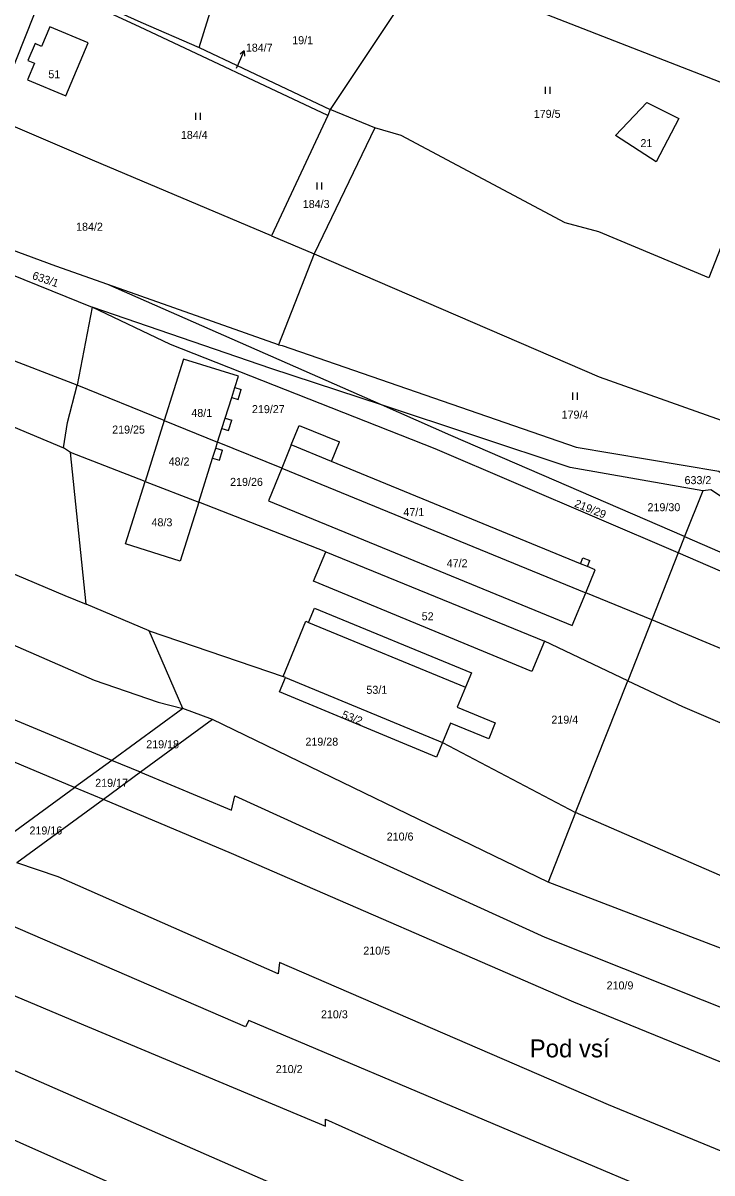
# Model space of a CAD drawing. Extents: x -744566 to -741843, y -1128407 to -1126744.
# Drawn here: x -742903.8 to -742757.6, y -1127789.3 to -1127545.1 of the extents above; entities that cross this region are included whole.
import ezdxf

# ---------------------------------------------------------------- set-up
doc = ezdxf.new("R2010")
doc.units = 0
for name, color, linetype in [('Hranice parcel', 7, 'Continuous'), ('Parcelní čísla', 7, 'Continuous'), ('Pop  PČ popisy', 7, 'Continuous'), ('Vnitřní kresba', 7, 'Continuous'), ('Značky kultur', 7, 'Continuous')]:
    doc.layers.add(name, color=color, linetype=linetype)

msp = doc.modelspace()

# ---------------------------------------------------------------- linework, layer by layer
at = {"layer": 'Hranice parcel'}
for p, q in [((-742818.41, -1127533.18), (-742838.56, -1127563.45)), ((-742818.41, -1127533.18), (-742743.76, -1127562.35)), ((-742866.42, -1127550.29), (-742838.56, -1127563.45)), ((-742838.56, -1127563.45), (-742839.05, -1127564.77)), ((-742829.14, -1127567.37), (-742838.56, -1127563.45)), ((-742839.05, -1127564.77), (-742851.05, -1127590.28)), ((-742829.14, -1127567.37), (-742842.01, -1127594.12)), ((-742851.05, -1127590.28), (-742842.01, -1127594.12)), ((-742919.33, -1127593.19), (-742889.07, -1127605.41)), ((-742842.01, -1127594.12), (-742849.54, -1127613.47)), ((-742827.7, -1127626.22), (-742885.79, -1127600.64)), ((-742849.54, -1127613.47), (-742885.79, -1127600.64)), ((-742889.07, -1127605.41), (-742892.31, -1127622.04)), ((-742892.31, -1127622.04), (-742925.74, -1127609.17)), ((-742873.81, -1127629.53), (-742892.31, -1127622.04)), ((-742873.81, -1127629.53), (-742877.87, -1127642.45)), ((-742873.81, -1127629.53), (-742862.47, -1127634.12)), ((-742848.87, -1127639.63), (-742862.47, -1127634.12)), ((-742893.68, -1127636.29), (-742895.2, -1127635.33)), ((-742890.34, -1127668.53), (-742893.68, -1127636.29)), ((-742877.87, -1127642.45), (-742893.68, -1127636.29)), ((-742848.87, -1127639.63), (-742784.35, -1127666.12)), ((-742877.87, -1127642.45), (-742866.48, -1127646.88)), ((-742839.52, -1127657.38), (-742866.48, -1127646.88)), ((-742759.53, -1127644.48), (-742763.36, -1127654.17)), ((-742763.36, -1127654.17), (-742764.73, -1127657.63)), ((-742839.52, -1127657.38), (-742793.13, -1127676.4)), ((-742764.73, -1127657.63), (-742770.35, -1127671.87)), ((-742770.35, -1127671.87), (-742784.35, -1127666.12)), ((-742877.02, -1127674.2), (-742890.34, -1127668.53)), ((-742770.35, -1127671.87), (-742775.45, -1127684.77)), ((-742877.02, -1127674.2), (-742848.58, -1127683.87)), ((-742869.86, -1127690.69), (-742877.02, -1127674.2)), ((-742775.45, -1127684.77), (-742793.13, -1127676.4)), ((-742848.05, -1127684.09), (-742848.58, -1127683.87)), ((-742848.05, -1127684.09), (-742814.73, -1127697.87)), ((-742786.49, -1127712.73), (-742775.45, -1127684.77)), ((-742869.86, -1127690.69), (-742884.93, -1127701.69)), ((-742863.54, -1127693.04), (-742869.86, -1127690.69)), ((-742863.54, -1127693.04), (-742878.82, -1127704.23)), ((-742792.35, -1127727.57), (-742863.54, -1127693.04)), ((-742814.73, -1127697.87), (-742786.49, -1127712.73)), ((-742884.93, -1127701.69), (-742892.82, -1127707.45)), ((-742878.82, -1127704.23), (-742884.93, -1127701.69)), ((-742878.82, -1127704.23), (-742886.72, -1127710.02)), ((-742911.19, -1127720.85), (-742892.82, -1127707.45)), ((-742886.72, -1127710.02), (-742892.82, -1127707.45)), ((-742886.72, -1127710.02), (-742905.07, -1127723.45)), ((-742786.49, -1127712.73), (-742792.35, -1127727.57)), ((-742663.65, -1127776.96), (-742792.35, -1127727.57))]:
    msp.add_line(p, q, dxfattribs=at)
for points in [[(-742866.42, -1127550.29), (-742864.4, -1127543.94), (-742860.9, -1127533.04), (-742859.94, -1127530.06), (-742866.48, -1127528.08), (-742868.86, -1127527.7), (-742866.81, -1127522.06)], [(-742839.05, -1127564.77), (-742879.04, -1127545.88), (-742898.83, -1127536.68)], [(-742898.55, -1127535.95), (-742878.8, -1127544.89), (-742866.42, -1127550.29)], [(-742909.93, -1127565.28), (-742909.31, -1127563.59), (-742907.18, -1127557.98), (-742901.31, -1127543.14)], [(-742901.23, -1127549.47), (-742902.74, -1127553.05), (-742901.33, -1127553.64), (-742902.81, -1127557.15), (-742894.7, -1127560.58), (-742889.94, -1127549.3), (-742898.05, -1127545.88), (-742899.82, -1127550.06), (-742901.23, -1127549.47)], [(-742743.76, -1127562.35), (-742758.22, -1127599.23), (-742781.54, -1127589.48), (-742788.73, -1127587.57), (-742823.54, -1127569.02), (-742829.14, -1127567.37)], [(-742771.4, -1127562), (-742764.6, -1127565.4), (-742769.4, -1127574.6), (-742778, -1127569), (-742771.4, -1127562)], [(-742851.05, -1127590.28), (-742889.01, -1127574.21), (-742909.93, -1127565.28)], [(-742885.79, -1127600.64), (-742896.8, -1127596.74), (-742927.53, -1127585.44)], [(-742842.01, -1127594.12), (-742781.53, -1127620.27), (-742738.25, -1127635.58), (-742671.97, -1127665.27), (-742626.86, -1127683.46)], [(-742764.73, -1127657.63), (-742816.28, -1127635.5), (-742872.48, -1127613.38), (-742889.07, -1127605.41)], [(-742827.7, -1127626.22), (-742851.21, -1127618.45), (-742889.07, -1127605.41)], [(-742849.54, -1127613.47), (-742848.76, -1127613.6), (-742786.4, -1127635.17), (-742756.11, -1127640.29), (-742704.21, -1127675.14), (-742663.56, -1127694.46), (-742647.49, -1127700.26), (-742632.48, -1127703.04)], [(-742862.47, -1127634.12), (-742861.56, -1127631.22), (-742860.87, -1127629.02), (-742859.48, -1127624.6), (-742858.82, -1127622.5), (-742858.07, -1127620.11), (-742869.71, -1127616.46), (-742873.81, -1127629.53)], [(-742933.59, -1127619.25), (-742932.84, -1127619.53), (-742895.2, -1127635.33)], [(-742895.2, -1127635.33), (-742894.34, -1127629.94), (-742892.31, -1127622.04)], [(-742759.53, -1127644.48), (-742787.62, -1127639.47), (-742827.7, -1127626.22)], [(-742763.36, -1127654.17), (-742813.01, -1127632.69), (-742827.7, -1127626.22)], [(-742866.48, -1127646.88), (-742863.54, -1127637.53), (-742862.87, -1127635.39), (-742862.47, -1127634.12)], [(-742966.93, -1127635.29), (-742957.86, -1127639.93), (-742940.86, -1127647.2), (-742894.92, -1127666.66), (-742890.34, -1127668.53)], [(-742784.35, -1127666.12), (-742782.33, -1127661.21), (-742783.99, -1127660.53), (-742785.47, -1127659.92), (-742838.33, -1127638.19), (-742846.84, -1127634.7), (-742848.87, -1127639.63)], [(-742989.43, -1127637.82), (-742962.79, -1127651.94), (-742947.37, -1127659.01), (-742888.66, -1127684.65), (-742875.08, -1127689.31), (-742869.86, -1127690.69)], [(-742848.87, -1127639.63), (-742851.71, -1127646.54), (-742787.2, -1127673.06), (-742784.35, -1127666.12)], [(-742866.48, -1127646.88), (-742870.4, -1127659.37), (-742882.04, -1127655.72), (-742877.87, -1127642.45)], [(-742664.42, -1127698.33), (-742705.7, -1127678.8), (-742757.77, -1127644.27), (-742759.53, -1127644.48)], [(-742884.93, -1127701.69), (-742931.01, -1127682.52), (-742982.33, -1127658.51), (-742997.69, -1127649.67)], [(-742763.36, -1127654.17), (-742748.4, -1127660.64), (-742692.32, -1127686.56), (-742664.42, -1127698.33)], [(-742892.82, -1127707.45), (-742959.07, -1127679.57), (-742986.2, -1127666.67), (-743003.07, -1127657.38)], [(-742793.13, -1127676.4), (-742795.78, -1127682.8), (-742842.1, -1127663.63), (-742839.52, -1127657.38)], [(-742640.13, -1127711.82), (-742707.48, -1127684.6), (-742751.48, -1127663.32), (-742764.73, -1127657.63)], [(-742848.58, -1127683.87), (-742843.74, -1127672.16), (-742843.19, -1127672.39), (-742841.94, -1127669.37), (-742808.61, -1127683.09), (-742809.88, -1127686.17), (-742811.62, -1127690.36), (-742803.55, -1127693.7), (-742804.94, -1127697.11), (-742813.02, -1127693.76), (-742814.73, -1127697.87)], [(-742643.36, -1127725.63), (-742711.98, -1127696.17), (-742770.35, -1127671.87)], [(-742814.73, -1127697.87), (-742816.01, -1127700.98), (-742849.31, -1127687.14), (-742848.05, -1127684.09)], [(-742775.45, -1127684.77), (-742763.82, -1127690.28), (-742650.2, -1127739.03)], [(-742878.82, -1127704.23), (-742859.56, -1127712.24), (-742858.85, -1127709.24), (-742793.05, -1127739.22), (-742667.79, -1127789.16)], [(-742691.75, -1127791.9), (-742786.9, -1127753.03), (-742859.54, -1127721.45), (-742886.72, -1127710.02)], [(-742659.43, -1127765.34), (-742739.02, -1127733.43), (-742786.49, -1127712.73)], [(-742697.57, -1127810.08), (-742723.74, -1127797.75), (-742779.52, -1127774.85), (-742849.36, -1127744.61), (-742849.6, -1127747), (-742896.29, -1127726.42), (-742905.07, -1127723.45)], [(-742705.33, -1127822.31), (-742752.11, -1127800.85), (-742855.88, -1127756.96), (-742856.57, -1127758.28), (-742916.95, -1127732.14)], [(-742929.76, -1127741.52), (-742892.25, -1127757.26), (-742839.56, -1127779.37), (-742839.56, -1127777.92), (-742777.16, -1127805.95), (-742712.92, -1127837.01)], [(-742942.9, -1127751.14), (-742921.78, -1127760.46), (-742847.12, -1127793.15), (-742812.02, -1127809), (-742724.3, -1127849.19), (-742701.43, -1127856.81), (-742666.84, -1127871.89)], [(-742670.28, -1127883.77), (-742733.59, -1127858.01), (-742796.71, -1127830.89), (-742912.22, -1127779.41), (-742955.04, -1127760.03)]]:
    msp.add_lwpolyline(points, dxfattribs=at)
at = {"layer": 'Pop  PČ popisy'}
for p, q in [((-742858.03, -1127553.74), (-742856.809, -1127550.998)), ((-742856.809, -1127550.998), (-742857.674, -1127551.71)), ((-742856.809, -1127550.998), (-742856.759, -1127552.117)), ((-742858.45, -1127554.67), (-742858.03, -1127553.74))]:
    msp.add_line(p, q, dxfattribs=at)
at = {"layer": 'Vnitřní kresba'}
for p, q in [((-742859.48, -1127624.6), (-742858.11, -1127625.03)), ((-742858.82, -1127622.5), (-742857.45, -1127622.93)), ((-742858.11, -1127625.03), (-742857.45, -1127622.93)), ((-742860.87, -1127629.02), (-742859.49, -1127629.46)), ((-742860.18, -1127631.65), (-742859.49, -1127629.46)), ((-742861.56, -1127631.22), (-742860.18, -1127631.65)), ((-742846.84, -1127634.7), (-742845.14, -1127630.56)), ((-742845.14, -1127630.56), (-742836.62, -1127634.03)), ((-742838.33, -1127638.19), (-742836.62, -1127634.03)), ((-742862.87, -1127635.39), (-742861.43, -1127635.84)), ((-742862.11, -1127637.97), (-742861.43, -1127635.84)), ((-742863.54, -1127637.53), (-742862.11, -1127637.97)), ((-742785.47, -1127659.92), (-742784.96, -1127658.67)), ((-742784.96, -1127658.67), (-742783.48, -1127659.28)), ((-742783.99, -1127660.53), (-742783.48, -1127659.28)), ((-742843.19, -1127672.39), (-742809.88, -1127686.17))]:
    msp.add_line(p, q, dxfattribs=at)
at = {"layer": 'Značky kultur'}
for p, q in [((-742792.871, -1127560.14), (-742792.871, -1127558.64)), ((-742791.87, -1127560.14), (-742791.87, -1127558.64)), ((-742867.121, -1127565.68), (-742867.121, -1127564.18)), ((-742866.12, -1127565.68), (-742866.12, -1127564.18)), ((-742841.371, -1127580.49), (-742841.371, -1127578.99)), ((-742840.37, -1127580.49), (-742840.37, -1127578.99)), ((-742787.111, -1127625.1), (-742787.111, -1127623.6)), ((-742786.11, -1127625.1), (-742786.11, -1127623.6))]:
    msp.add_line(p, q, dxfattribs=at)

# ---------------------------------------------------------------- texts
at = {"layer": 'Parcelní čísla'}
for s, p in [('19/1', (-742846.641, -1127549.6)), ('184/7', (-742856.48, -1127551.18)), ('51', (-742898.392, -1127556.83)), ('179/5', (-742795.38, -1127565.24)), ('184/4', (-742870.273, -1127569.72)), ('21', (-742772.742, -1127571.46)), ('184/3', (-742844.403, -1127584.39)), ('184/2', (-742892.513, -1127589.21)), ('48/1', (-742868.05, -1127628.76)), ('219/27', (-742855.19, -1127627.95)), ('179/4', (-742789.47, -1127629.11)), ('219/25', (-742884.85, -1127632.29)), ('48/2', (-742872.87, -1127639.07)), ('219/26', (-742859.82, -1127643.4)), ('633/2', (-742763.38, -1127643.03)), ('47/1', (-742823.05, -1127649.81)), ('219/30', (-742771.24, -1127648.78)), ('48/3', (-742876.5, -1127651.98)), ('47/2', (-742813.86, -1127660.68)), ('52', (-742819.162, -1127671.94)), ('53/1', (-742830.9, -1127687.56)), ('219/4', (-742791.64, -1127693.89)), ('219/18', (-742877.62, -1127699.12)), ('219/28', (-742843.84, -1127698.57)), ('219/17', (-742888.45, -1127707.31)), ('219/16', (-742902.4, -1127717.43)), ('210/6', (-742826.59, -1127718.72)), ('210/5', (-742831.56, -1127742.95)), ('210/9', (-742779.92, -1127750.33)), ('210/3', (-742840.54, -1127756.47)), ('210/2', (-742850.13, -1127768.1))]:
    msp.add_text(s, height=1.7, dxfattribs=at).set_placement(p)
for s, rotation, p in [('633/1', 341, (-742901.956, -1127599.403)), ('219/29', 338, (-742786.908, -1127647.768)), ('53/2', 339, (-742836.264, -1127692.633))]:
    msp.add_text(s, height=1.7, rotation=rotation, dxfattribs=at).set_placement(p)
at = {"layer": 'Pop  PČ popisy'}
msp.add_text('Pod vsí', height=3.8, dxfattribs=at).set_placement((-742796.24, -1127764.76))

doc.saveas('drawing.dxf')
